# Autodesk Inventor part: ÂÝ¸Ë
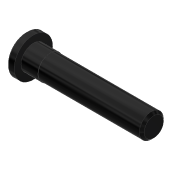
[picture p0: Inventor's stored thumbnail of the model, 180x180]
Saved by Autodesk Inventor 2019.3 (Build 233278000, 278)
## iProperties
Created: 2017-10
Part Number: ÂÝ¸Ë
Material: Ogólny
Document SubType Name: Modeling
Designer: CADENGINEERING4
Density: 1 g/cm^3
Appearance: Gładki — czarny
Author: CADENGINEERING4
Revision Number: ÈÎºÎ
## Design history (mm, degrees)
feature "Ðý×ª1"
node "Bryła1"
